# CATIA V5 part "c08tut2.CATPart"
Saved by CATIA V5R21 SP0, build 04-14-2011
Part number: Part1
Bounding box of the stored display mesh (mm): x -50.5 to 35, y -44.738 to 44.738, z 0 to 30.5
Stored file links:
  D:\CATIA V5R21 E-RESOURCES\CATIA-V5R21\catia-v5r21-prt\c08-catia-v5r20-prt\c08-catia-v5r21-tut02.CATPart
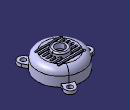
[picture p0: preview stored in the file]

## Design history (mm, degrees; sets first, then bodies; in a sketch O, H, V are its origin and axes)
Body1 (main body)
  Sketch1 on yz-plane, origin (0, 0, 0), H (0, 1, 0), V (0, 0, 1)
    line L1 (0, 0) -> (35, 0)
    line L2 (35, 0) -> (35, 15)
    arc A1 centre (25, 15) radius 10 from (35, 15) to (25, 25) ccw
    line L3 (25, 25) -> (0, 25)
    point P5 (0, 25)
    line L4 (0, 25) -> (0, 0)
    axis line L5 (0, 70.1891) -> (0, -36.6898)
    point P6 (0, 70.1891)
    "Radius" L2 L5 = 35
    distance L1 L3 = 25
    radius A1 = 10
    horizontal: L1 H
    vertical: L2 V, L4 V, L5 V
    tangency: A1 L2, L3 A1
    coincidence: P5 V, P6 V
  Shaft1: profile Sketch1, axis Sketch1.L5, angle 360
  Shell1: ExtOffset 0, Face face of Shaft1, IntOffset 2.5
  Sketch2 on face of Shaft1, origin (0, 0, 0), H (1, 0, 0), V (0, -1, 0)
    projected circle E1 centre (0, 0) radius 35 from edge [face of Shaft1 | face of Shaft1]
    projected arc E2 centre (0, 0) radius 35 from (-34.0735, 8) to (-34.0735, -8) ccw from edge [face of Shaft1 | face of Shaft1]
    point P1 (-34.0735, 8)
    line L1 (-34.0735, 8) -> (-42.5, 8)
    arc A1 centre (-42.5, 0) radius 8 from (-42.5, 8) to (-42.5, -8) ccw
    point P3 (-42.5, 0)
    line L2 (-42.5, -8) -> (-34.0735, -8)
    point P5 (-34.0735, -8)
    circle A2 centre (-42.5, 0) radius 4
    distance P3 V = 42.5
    radius A1 = 8
    radius A2 = 4
    coincidence: P1 E1, P5 E1, P3 H
    horizontal: L1 H, L2 H
    tangency: A1 L1, L2 A1
  Pad1: profile Sketch2, direction (0, 0, 1), length 5
  CircPattern1: of Pad1, instances 3, angular step 120 {= 360.0*1 deg/CircPattern1.AngularNumber}, axis from face of Shaft1
  Sketch3 on face of Shaft1, origin (0, 0, 25), H (1, 0, 0), V (0, 1, 0)
    construction line L1 (-20, -18) -> (20, -18)
    point P2 (20, -18)
    line L2 (-20, -16.25) -> (20, -16.25)
    line L3 (20, -19.75) -> (-20, -19.75)
    arc A1 centre (20, -18) radius 1.75 from (20, -16.25) to (20, -19.75) cw
    arc A2 centre (-20, -18) radius 1.75 from (-20, -19.75) to (-20, -16.25) cw
    length L1 = 40
    distance H L1 = 18
    distance P2 V = 20
    distance L3 L2 = 3.5
    horizontal: L1 H
    tangency: A1 L2, A2 L2, A1 L3, A2 L3
    parallelism: L1 L2
  Pocket1: profile Sketch3, direction (0, 0, -1), length 5
  RectPattern1: of Pocket1, direction 1 instances 7, spacing 6, along yz-plane
  Sketch4 on face of Shell1, origin (0, 0, 22.5), H (1, 0, 0), V (0, -1, 0)
    circle A1 centre (0, 0) radius 12.5
    radius A1 = 12.5
  Pad2: profile Sketch4, direction (0, 0, 1), length 8
  Fillet1: radius 2, on edge [end face of Pad2 | face of Pad2 from Sketch4.A1]
  Sketch5 on face of Pad2, origin (0, 0, 22.5), H (1, 0, 0), V (0, -1, 0)
    circle A1 centre (0, 0) radius 7.5
    radius A1 = 7.5
  Pocket2: profile Sketch5, direction (0, 0, 1), through (limit type 3)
